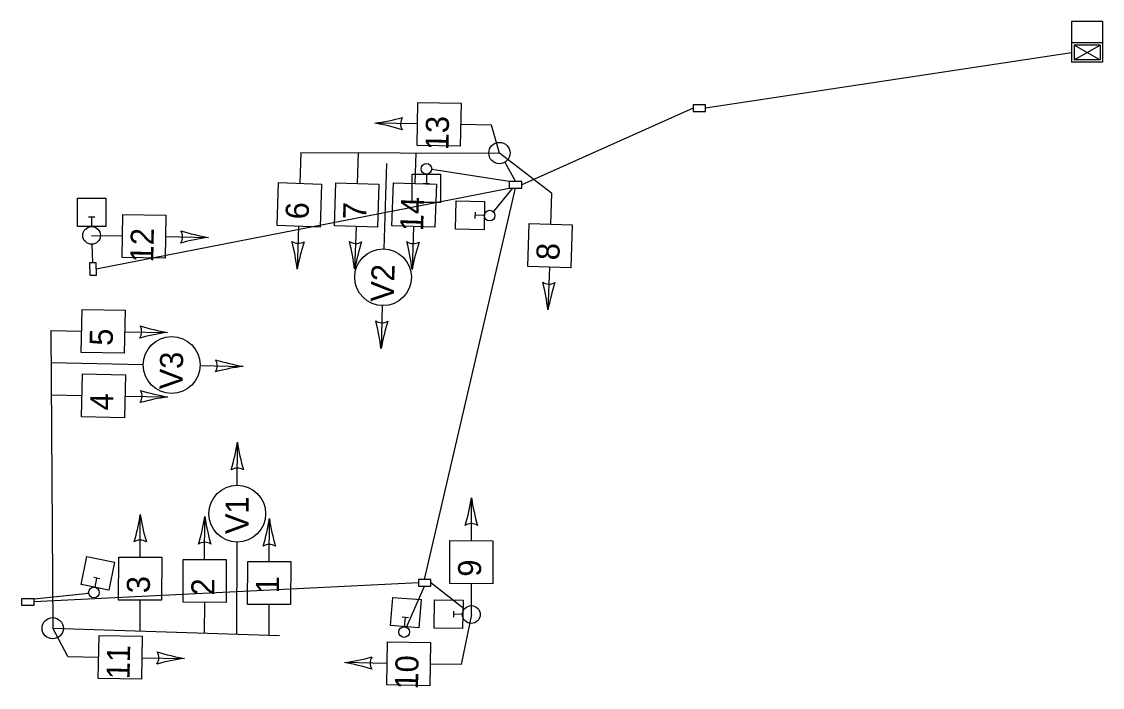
# Model space of a CAD drawing. Extents: x 993729 to 994927, y 1984823 to 1986420.
# Drawn here: x 994774.5 to 994926.9, y 1984822.5 to 1984916.4 of the extents above; entities that cross this region are included whole.
import ezdxf

# ---------------------------------------------------------------- set-up
doc = ezdxf.new("R2010")
doc.units = 0
for name, color, linetype in [('EX_BREAKLINE_PT_SYM', 7, 'Continuous'), ('EX_FLAG_POLE', 7, 'Continuous'), ('EX_GAS_UTILITIES', 7, 'Continuous'), ('EX_LANDSCAPING', 7, 'Continuous'), ('EX_MSC_PT_SYM', 7, 'Continuous'), ('EX_STORM_SEWER', 7, 'Continuous')]:
    doc.layers.add(name, color=color, linetype=linetype)

msp = doc.modelspace()

# ---------------------------------------------------------------- linework, layer by layer
at = {"layer": 'EX_BREAKLINE_PT_SYM'}
for p, q in [((994830.35, 1984901.99), (994824.31, 1984902.1)), ((994840.76, 1984901.81), (994836.41, 1984901.9)), ((994841.88, 1984897.88), (994840.76, 1984901.81)), ((994813.88, 1984897.96), (994813.74, 1984893.61)), ((994821.99, 1984897.94), (994821.84, 1984893.59)), ((994830.09, 1984897.91), (994829.94, 1984893.57)), ((994849.23, 1984892.2), (994841.88, 1984897.88)), ((994825.95, 1984896.41), (994825.6, 1984884.36)), ((994849.23, 1984892.2), (994849.09, 1984887.85)), ((994813.57, 1984887.55), (994813.37, 1984881.51)), ((994821.67, 1984887.53), (994821.47, 1984881.49)), ((994829.77, 1984887.51), (994829.57, 1984881.47)), ((994784.4, 1984886.27), (994788.75, 1984886.19)), ((994794.81, 1984886.09), (994800.85, 1984885.98)), ((994848.92, 1984881.79), (994848.72, 1984875.76)), ((994825.36, 1984876.37), (994825.19, 1984870.31)), ((994778.65, 1984872.87), (994782.99, 1984872.78)), ((994789.05, 1984872.69), (994795.09, 1984872.58)), ((994778.67, 1984868.32), (994791.68, 1984868.07)), ((994799.68, 1984867.92), (994805.74, 1984867.8)), ((994778.7, 1984863.77), (994783.05, 1984863.68)), ((994789.11, 1984863.59), (994795.15, 1984863.48)), ((994804.93, 1984851.02), (994804.95, 1984857.09)), ((994837.92, 1984843.21), (994837.94, 1984849.25)), ((994791.24, 1984840.87), (994791.25, 1984846.91)), ((994800.33, 1984840.58), (994800.35, 1984846.62)), ((994809.43, 1984840.28), (994809.45, 1984846.32)), ((994804.88, 1984830.02), (994804.91, 1984843.02)), ((994837.92, 1984832.8), (994837.93, 1984837.15)), ((994791.24, 1984830.46), (994791.25, 1984834.81)), ((994800.33, 1984830.17), (994800.34, 1984834.51)), ((994809.43, 1984829.87), (994809.44, 1984834.21)), ((994837.92, 1984832.8), (994836.47, 1984825.73)), ((994781.05, 1984826.89), (994778.91, 1984830.87)), ((994781.05, 1984826.89), (994785.4, 1984826.8)), ((994791.46, 1984826.71), (994797.5, 1984826.6)), ((994826.06, 1984825.9), (994820.02, 1984826.02)), ((994836.47, 1984825.73), (994832.12, 1984825.81))]:
    msp.add_line(p, q, dxfattribs=at)
for points in [[(994836.47, 1984904.91), (994836.35, 1984898.85), (994830.29, 1984898.96), (994830.4, 1984905.03)], [(994816.79, 1984893.51), (994816.59, 1984887.45), (994810.53, 1984887.65), (994810.73, 1984893.71)], [(994824.89, 1984893.49), (994824.69, 1984887.43), (994818.63, 1984887.63), (994818.83, 1984893.69)], [(994832.99, 1984893.47), (994832.79, 1984887.41), (994826.73, 1984887.61), (994826.93, 1984893.67)], [(994794.87, 1984889.12), (994794.76, 1984883.05), (994788.69, 1984883.17), (994788.81, 1984889.23)], [(994852.14, 1984887.75), (994851.94, 1984881.69), (994845.88, 1984881.89), (994846.08, 1984887.95)], [(994789.11, 1984875.72), (994789, 1984869.65), (994782.93, 1984869.77), (994783.05, 1984875.83)], [(994789.17, 1984866.62), (994789.05, 1984860.55), (994782.99, 1984860.67), (994783.11, 1984866.73)], [(994840.96, 1984843.21), (994840.95, 1984837.14), (994834.88, 1984837.16), (994834.9, 1984843.22)], [(994794.28, 1984840.87), (994794.26, 1984834.8), (994788.2, 1984834.82), (994788.21, 1984840.88)], [(994803.37, 1984840.57), (994803.36, 1984834.5), (994797.3, 1984834.52), (994797.31, 1984840.58)], [(994812.47, 1984840.27), (994812.45, 1984834.21), (994806.39, 1984834.22), (994806.41, 1984840.29)], [(994791.52, 1984829.74), (994791.41, 1984823.67), (994785.34, 1984823.79), (994785.46, 1984829.85)], [(994832.18, 1984828.83), (994832.07, 1984822.76), (994826, 1984822.88), (994826.12, 1984828.94)]]:
    msp.add_lwpolyline(points, close=True, dxfattribs=at)
for centre in [(994825.48, 1984880.37), (994795.68, 1984867.99), (994804.92, 1984847.02)]:
    msp.add_circle(centre, 4, dxfattribs=at)
for centre, radius, start, end in [((994820.45, 1984931.32), 29.47, 277.5232, 285.2613), ((994829.57, 1984902), 1.63, 147.0676, 210.7622), ((994819.34, 1984873.05), 29.47, 72.5685, 80.3066), ((994795.59, 1984886.08), 1.63, 327.0676, 30.7622), ((994804.71, 1984856.76), 29.47, 97.5232, 105.2613), ((994805.82, 1984915.03), 29.47, 252.5685, 260.3066), ((994813.54, 1984886.78), 1.63, 236.2765, 299.9711), ((994784.1, 1984878.06), 29.47, 6.7321, 14.4702), ((994842.35, 1984876.15), 29.47, 161.7773, 169.5155), ((994821.64, 1984886.76), 1.63, 236.2765, 299.9711), ((994792.2, 1984878.04), 29.47, 6.7321, 14.4702), ((994850.45, 1984876.13), 29.47, 161.7773, 169.5155), ((994829.74, 1984886.74), 1.63, 236.2765, 299.9711), ((994800.3, 1984878.02), 29.47, 6.7321, 14.4702), ((994858.55, 1984876.11), 29.47, 161.7773, 169.5155), ((994848.89, 1984881.02), 1.63, 236.2765, 299.9711), ((994819.45, 1984872.3), 29.47, 6.7321, 14.4702), ((994877.7, 1984870.39), 29.47, 161.7773, 169.5155), ((994825.34, 1984875.57), 1.63, 236.4841, 300.1787), ((994795.93, 1984866.74), 29.47, 6.9397, 14.6778), ((994854.19, 1984865.05), 29.47, 161.985, 169.7231), ((994789.83, 1984872.68), 1.63, 327.0676, 30.7622), ((994798.95, 1984843.36), 29.47, 97.5232, 105.2613), ((994800.06, 1984901.63), 29.47, 252.5685, 260.3066), ((994800.48, 1984867.9), 1.63, 327.0676, 30.7622), ((994809.6, 1984838.59), 29.47, 97.5232, 105.2613), ((994810.7, 1984896.85), 29.47, 252.5685, 260.3066), ((994789.88, 1984863.58), 1.63, 327.0676, 30.7622), ((994799.01, 1984834.26), 29.47, 97.5232, 105.2613), ((994800.11, 1984892.53), 29.47, 252.5685, 260.3066), ((994775.82, 1984861.58), 29.47, 343.5009, 351.2391), ((994834.1, 1984861.42), 29.47, 188.4557, 196.1938), ((994804.94, 1984851.82), 1.63, 58.0001, 121.6947), ((994808.81, 1984853.74), 29.47, 343.5081, 351.2462), ((994867.09, 1984853.59), 29.47, 188.4628, 196.2009), ((994762.13, 1984851.4), 29.47, 343.5081, 351.2462), ((994820.41, 1984851.25), 29.47, 188.4628, 196.2009), ((994771.22, 1984851.1), 29.47, 343.5081, 351.2462), ((994829.5, 1984850.95), 29.47, 188.4628, 196.2009), ((994780.32, 1984850.8), 29.47, 343.5081, 351.2462), ((994838.6, 1984850.66), 29.47, 188.4628, 196.2009), ((994837.92, 1984843.99), 1.63, 58.0072, 121.7018), ((994791.24, 1984841.65), 1.63, 58.0072, 121.7018), ((994800.34, 1984841.35), 1.63, 58.0072, 121.7018), ((994809.43, 1984841.05), 1.63, 58.0072, 121.7018), ((994792.24, 1984826.7), 1.63, 327.0676, 30.7622), ((994801.36, 1984797.38), 29.47, 97.5232, 105.2613), ((994802.46, 1984855.65), 29.47, 252.5685, 260.3066), ((994816.16, 1984855.24), 29.47, 277.5232, 285.2613), ((994825.29, 1984825.92), 1.63, 147.0676, 210.7622), ((994815.06, 1984796.97), 29.47, 72.5685, 80.3066)]:
    msp.add_arc(centre, radius, start, end, dxfattribs=at)
at = {"layer": 'EX_FLAG_POLE'}
for p, q in [((994922.54, 1984912), (994870.95, 1984904.22)), ((994869.2, 1984904.22), (994845.02, 1984893.41)), ((994842.62, 1984896.58), (994844.15, 1984893.87)), ((994843.27, 1984893.87), (994832.33, 1984895.54)), ((994785.06, 1984881.55), (994843.27, 1984892.95)), ((994831.34, 1984837.73), (994844.15, 1984892.95)), ((994843.74, 1984892.95), (994841.01, 1984889.61)), ((994784.58, 1984882.41), (994784.46, 1984885.02)), ((994830.47, 1984837.27), (994776.28, 1984834.57)), ((994836.97, 1984833.55), (994832.22, 1984837.27)), ((994776.28, 1984835.03), (994783.99, 1984835.82)), ((994828.76, 1984831.01), (994831.34, 1984836.81))]:
    msp.add_line(p, q, dxfattribs=at)
at = {"layer": 'EX_GAS_UTILITIES'}
for points in [[(994833.59, 1984894.89), (994833.58, 1984890.89), (994829.58, 1984890.9), (994829.59, 1984894.9)], [(994782.41, 1984887.52), (994782.42, 1984891.52), (994786.42, 1984891.51), (994786.41, 1984887.51)], [(994839.71, 1984887.07), (994835.71, 1984887.15), (994835.79, 1984891.15), (994839.79, 1984891.07)], [(994782.92, 1984837.04), (994783.72, 1984840.96), (994787.64, 1984840.16), (994786.84, 1984836.24)], [(994826.52, 1984831.24), (994826.84, 1984835.22), (994830.83, 1984834.9), (994830.51, 1984830.92)], [(994836.68, 1984830.82), (994832.68, 1984830.89), (994832.75, 1984834.89), (994836.75, 1984834.82)]]:
    msp.add_lwpolyline(points, close=True, dxfattribs=at)
at = {"layer": 'EX_LANDSCAPING'}
for p, q in [((994869.2, 1984904.68), (994869.2, 1984903.76)), ((994870.95, 1984904.68), (994869.2, 1984904.68)), ((994870.95, 1984903.76), (994870.95, 1984904.68)), ((994869.2, 1984903.76), (994870.95, 1984903.76)), ((994831.15, 1984893.58), (994832.02, 1984893.58)), ((994831.59, 1984894.9), (994831.58, 1984893.58)), ((994843.27, 1984893.87), (994843.27, 1984892.95)), ((994845.02, 1984893.87), (994843.27, 1984893.87)), ((994845.02, 1984892.95), (994845.02, 1984893.87)), ((994843.27, 1984892.95), (994845.02, 1984892.95)), ((994784.85, 1984888.83), (994783.98, 1984888.84)), ((994784.41, 1984887.52), (994784.42, 1984888.84)), ((994838.44, 1984889.53), (994838.42, 1984888.66)), ((994839.75, 1984889.07), (994838.43, 1984889.1)), ((994785.04, 1984882.42), (994784.12, 1984882.41)), ((994784.12, 1984882.41), (994784.15, 1984880.66)), ((994785.07, 1984880.67), (994785.04, 1984882.42)), ((994784.15, 1984880.66), (994785.07, 1984880.67)), ((994785.57, 1984837.84), (994784.72, 1984838.02)), ((994784.88, 1984836.64), (994785.15, 1984837.93)), ((994830.47, 1984837.73), (994830.47, 1984836.81)), ((994832.22, 1984837.73), (994830.47, 1984837.73)), ((994832.22, 1984836.81), (994832.22, 1984837.73)), ((994830.47, 1984836.81), (994832.22, 1984836.81)), ((994776.28, 1984835.03), (994774.53, 1984835.02)), ((994774.53, 1984835.02), (994774.53, 1984834.1)), ((994774.53, 1984834.1), (994776.28, 1984834.11)), ((994776.28, 1984834.11), (994776.28, 1984835.03)), ((994835.4, 1984833.28), (994835.39, 1984832.41)), ((994836.71, 1984832.82), (994835.4, 1984832.85)), ((994829.05, 1984832.35), (994828.18, 1984832.43)), ((994828.51, 1984831.08), (994828.62, 1984832.39))]:
    msp.add_line(p, q, dxfattribs=at)
at = {"layer": 'EX_MSC_PT_SYM'}
for p, q in [((994813.88, 1984897.96), (994841.88, 1984897.88)), ((994778.65, 1984872.87), (994778.91, 1984830.87)), ((994778.91, 1984830.87), (994810.89, 1984829.82))]:
    msp.add_line(p, q, dxfattribs=at)
for centre, radius in [((994841.88, 1984897.88), 1.5), ((994831.59, 1984895.65), 0.75), ((994840.5, 1984889.06), 0.75), ((994784.4, 1984886.27), 1.25), ((994784.73, 1984835.9), 0.75), ((994837.92, 1984832.8), 1.25), ((994778.91, 1984830.87), 1.5), ((994828.45, 1984830.33), 0.75)]:
    msp.add_circle(centre, radius, dxfattribs=at)
at = {"layer": 'EX_STORM_SEWER'}
for p, q in [((994922.54, 1984916.42), (994922.54, 1984910.68)), ((994926.87, 1984916.42), (994922.54, 1984916.42)), ((994926.87, 1984916.42), (994926.87, 1984910.68)), ((994926.87, 1984913.42), (994922.54, 1984913.42)), ((994926.54, 1984913.09), (994922.87, 1984913.09)), ((994926.52, 1984911.01), (994922.87, 1984913.09)), ((994922.87, 1984911.01), (994926.54, 1984913.09)), ((994922.87, 1984913.09), (994922.87, 1984911.01)), ((994926.54, 1984913.09), (994926.54, 1984911.01)), ((994926.87, 1984910.68), (994922.54, 1984910.68)), ((994926.54, 1984911.01), (994922.87, 1984911.01))]:
    msp.add_line(p, q, dxfattribs=at)

# ---------------------------------------------------------------- texts
at = {"layer": 'EX_BREAKLINE_PT_SYM'}
for s, rotation, p in [('13', 88.9149, (994834.69, 1984898.25)), ('6', 88.1238, (994814.97, 1984888.49)), ('7', 88.1238, (994823.07, 1984888.47)), ('14', 88.1238, (994831.12, 1984886.82)), ('12', 88.9149, (994793.09, 1984882.44)), ('8', 88.1238, (994850.32, 1984882.73)), ('V2', 88.3314, (994826.97, 1984876.85)), ('5', 88.9149, (994787.36, 1984870.68)), ('V3', 88.9149, (994797.21, 1984864.52)), ('4', 88.9149, (994787.42, 1984861.57)), ('V1', 89.8474, (994806.51, 1984844.14)), ('9', 89.8545, (994839.3, 1984838.13)), ('3', 89.8545, (994792.61, 1984835.8)), ('2', 89.8545, (994801.71, 1984835.48)), ('1', 89.8545, (994810.81, 1984835.77)), ('11', 88.9149, (994789.75, 1984823.64)), ('10', 88.9149, (994830.4, 1984822.19))]:
    msp.add_text(s, height=3.25, rotation=rotation, dxfattribs=at).set_placement(p)

doc.saveas('drawing.dxf')
